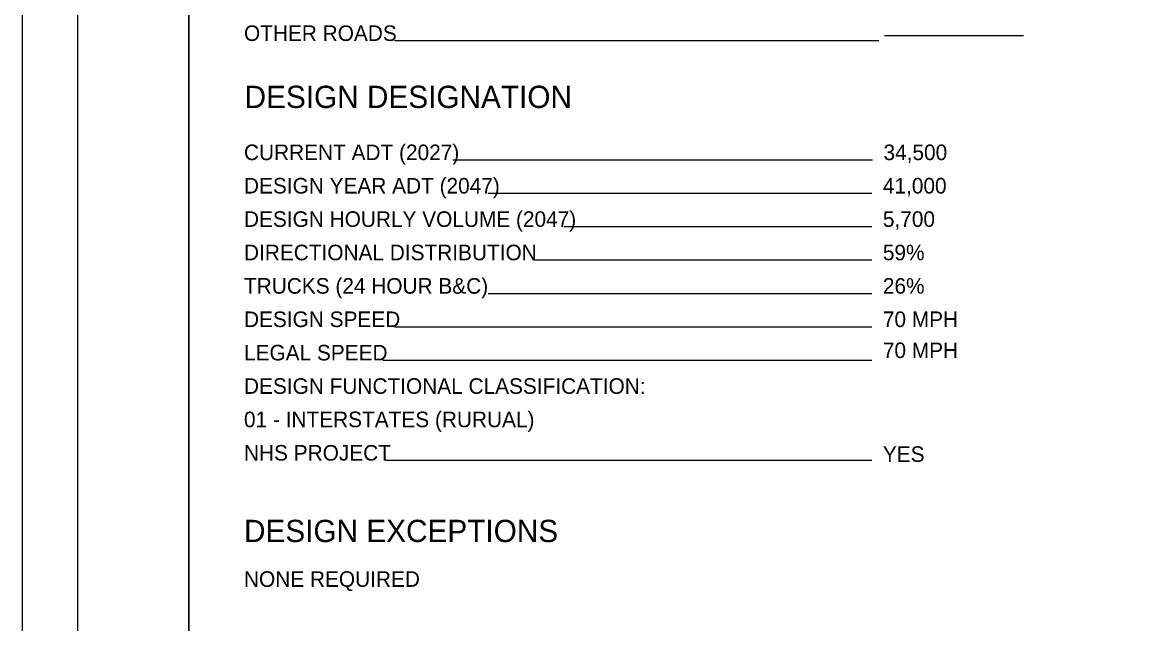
# Model space of a CAD drawing. Extents: x 0 to 34, y 0 to 22.
# Drawn here: x 0 to 9.93, y 5.64 to 11.05 of the extents above; entities that cross this region are included whole.
import ezdxf

# ---------------------------------------------------------------- set-up
doc = ezdxf.new("R2010")
doc.units = 0
for name, color, linetype in [('SH_Border', 7, 'Continuous'), ('SH_Cut_Line', 7, 'Continuous'), ('SH_Data', 7, 'Continuous'), ('SH_Text', 7, 'Continuous')]:
    doc.layers.add(name, color=color, linetype=linetype)

msp = doc.modelspace()

# ---------------------------------------------------------------- linework, layer by layer
at = {"layer": 'SH_Border'}
for points in [[(0.5, 21.5), (1.5, 21.5), (1.5, 0.5), (0.5, 0.5)], [(1.5, 21.5), (33.5, 21.5), (33.5, 0.5), (1.5, 0.5)]]:
    msp.add_lwpolyline(points, close=True, dxfattribs=at)
at = {"layer": 'SH_Cut_Line'}
msp.add_lwpolyline([(0, 0), (34, 0), (34, 22), (0, 22)], close=True, dxfattribs=at)
at = {"layer": 'SH_Data'}
for p, q in [((7.7, 10.8767), (3.3471, 10.8767)), ((9, 10.9223), (7.75, 10.9223)), ((7.6424, 9.8062), (3.871, 9.8062)), ((7.6368, 9.5062), (4.1885, 9.5062)), ((7.6368, 9.2062), (4.8723, 9.2062)), ((7.6368, 8.9062), (4.6037, 8.9062)), ((7.6368, 8.6062), (4.1885, 8.6062)), ((7.6368, 8.3062), (3.346, 8.3062)), ((7.6368, 8.0062), (3.2422, 8.0062)), ((7.6368, 7.1062), (3.2669, 7.1062))]:
    msp.add_line(p, q, dxfattribs=at)

# ---------------------------------------------------------------- texts
msp.add_text('DESIGN DESIGNATION', height=0.2, dxfattribs=at).set_placement((2, 10.2747))
at = {"layer": 'SH_Text'}
for s, height, p in [('OTHER ROADS', 0.14, (1.9944, 10.8767)), ('CURRENT ADT (2027)', 0.14, (1.9944, 9.8062)), ('34,500', 0.14, (7.7424, 9.8062)), ('DESIGN YEAR ADT (2047)', 0.14, (1.9944, 9.5062)), ('41,000', 0.14, (7.7368, 9.5062)), ('DESIGN HOURLY VOLUME (2047)', 0.14, (1.9944, 9.2062)), ('5,700', 0.14, (7.7368, 9.2062)), ('DIRECTIONAL DISTRIBUTION', 0.14, (1.9944, 8.9062)), ('59%', 0.14, (7.7368, 8.9062)), ('TRUCKS (24 HOUR B&C)', 0.14, (1.9944, 8.6062)), ('26%', 0.14, (7.7368, 8.6062)), ('DESIGN SPEED', 0.14, (1.9944, 8.3062)), ('70 MPH', 0.14, (7.7368, 8.3062)), ('LEGAL SPEED', 0.14, (1.9944, 8.0062)), ('70 MPH', 0.14, (7.7368, 8.0274)), ('DESIGN FUNCTIONAL CLASSIFICATION:', 0.14, (1.9944, 7.7062)), ('01 - INTERSTATES (RURUAL)', 0.14, (1.9944, 7.4062)), ('NHS PROJECT', 0.14, (1.9944, 7.1062)), ('YES', 0.14, (7.7368, 7.0944)), ('DESIGN EXCEPTIONS', 0.2, (1.9944, 6.3744)), ('NONE REQUIRED', 0.14, (1.9944, 5.972))]:
    msp.add_text(s, height=height, dxfattribs=at).set_placement(p)

doc.saveas('drawing.dxf')
